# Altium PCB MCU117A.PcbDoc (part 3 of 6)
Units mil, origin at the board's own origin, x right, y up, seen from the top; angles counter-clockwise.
Board outline 2300 x 6749.64 mil, 6 copper layers (Top Signal, GND, Middle Signal, PWR, GND2, Bottom Signal), stack 61.64 mil thick; 424 components, 343 nets, 1563 pads, 921 vias.
Unrouted connection lines stored in the file: 4.
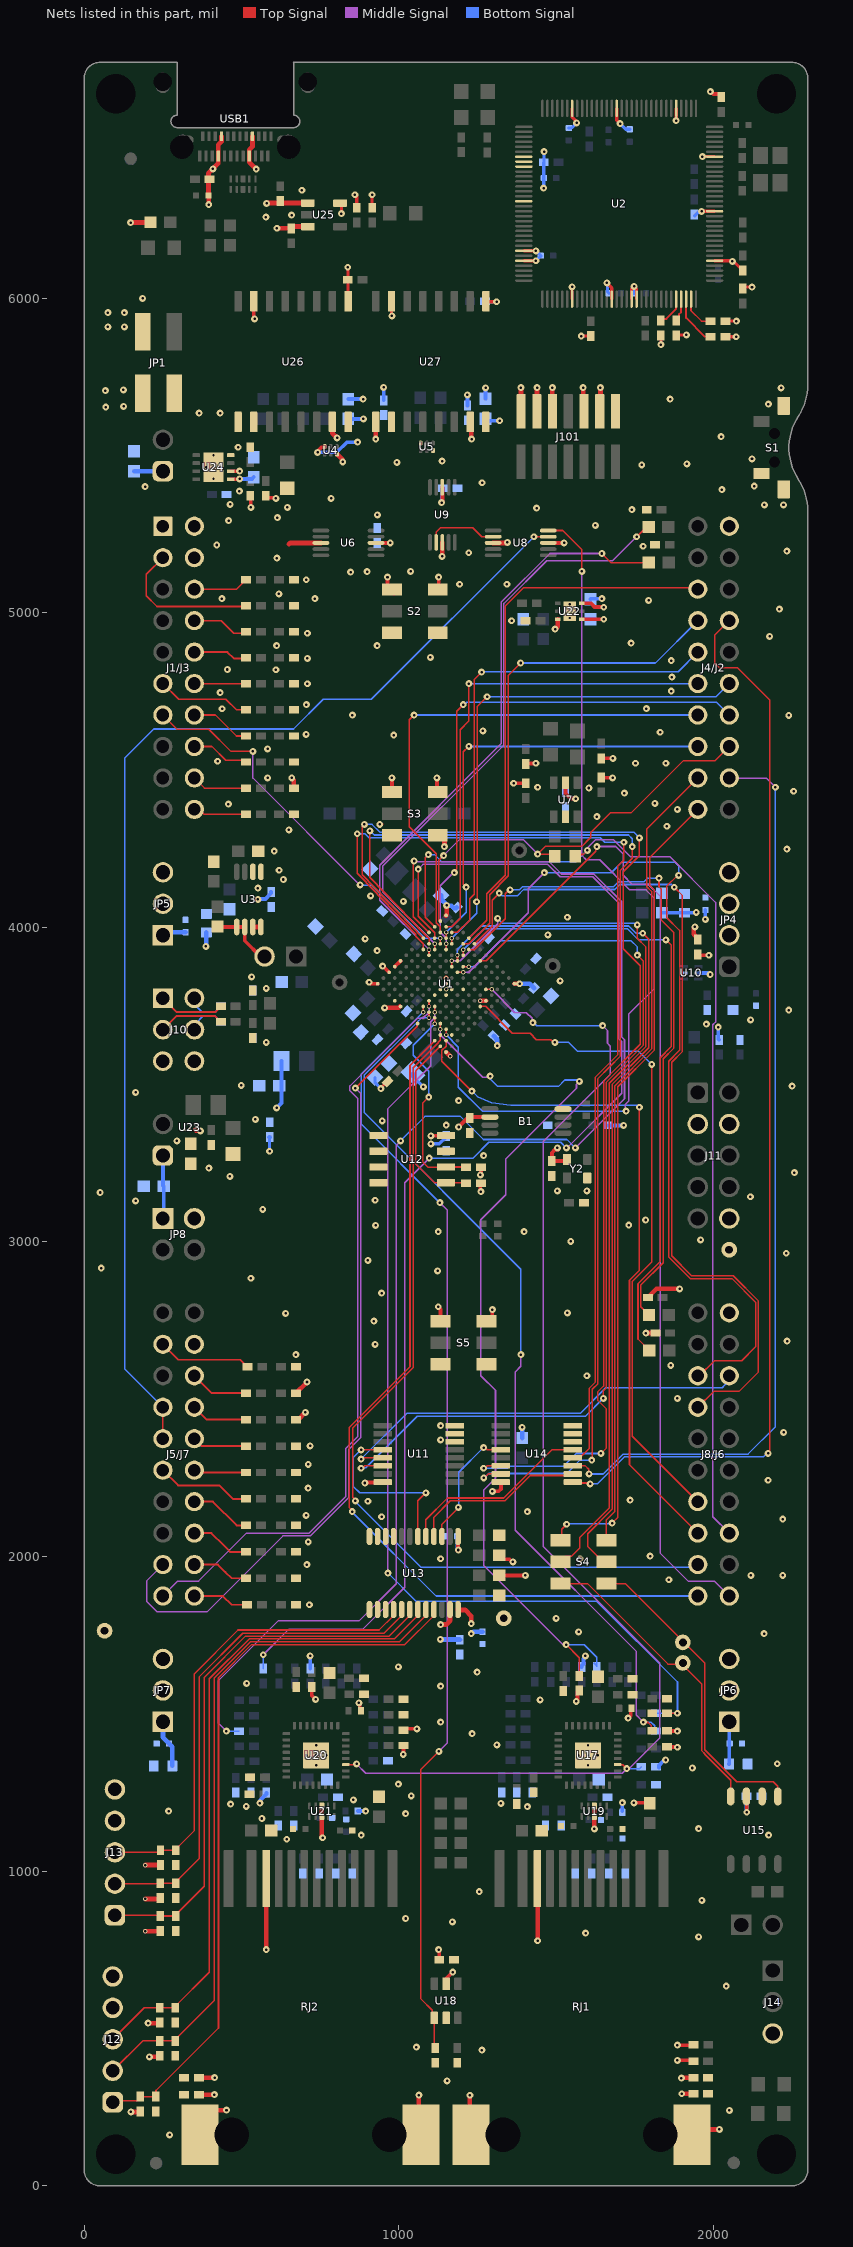
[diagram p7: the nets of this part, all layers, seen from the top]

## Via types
v1: diameter 22, hole 8, Top Signal to Bottom Signal, tented both sides, 821 vias
v2: diameter 14, hole 8, Top Signal to Bottom Signal, tented both sides, 82 vias
v3: diameter 19.68, hole 7.87, Top Signal to Bottom Signal, tented top, 14 vias
v4: diameter 15.75, hole 7.87, Top Signal to Bottom Signal, tented both sides, 2 vias
v5: diameter 19.68, hole 7.87, Top Signal to Bottom Signal, 2 vias

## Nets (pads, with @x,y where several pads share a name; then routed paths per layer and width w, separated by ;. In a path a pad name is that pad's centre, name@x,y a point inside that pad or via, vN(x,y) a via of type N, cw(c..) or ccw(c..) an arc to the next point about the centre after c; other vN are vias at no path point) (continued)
+3V3_ISO_JTAG: C130.1 C133.1 J101.1 R74.1 R76.1 U4.6 U5.6 U26.10 U26.16 U27.10 U27.16 | length 330
  Top Signal w12: v1(741.94,5509.65) 743.86,5511.56 743.86,5515.71 754.07,5525.92 763.86,5525.92 763.96,5526.02 U4.6@763.96,5527.8
  Bottom Signal w12: v1(741.94,5509.65) 802.41,5509.65 834.57,5541.81 v1(869.02,5541.81) ; R74.1@839.18,5678.86 v1(886.21,5678.86) ; v1(951.46,5715.99) 951.52,5715.93 C130.1@951.57,5674.88 C130.1@951.57,5674.88 ; v1(1217.84,5692.17) 1217.92,5692.08 1217.92,5658.7 C133.1@1218,5658.62 ; R76.1@1275.09,5679.5 1275.5,5679.91 v1(1275.5,5714.14)
+3V3_MCU: B1.6 C5.2 C12.2 C16.1 C17.2 C18.1 C19.1 C20.1 C21.1 C51.1 C60.1 C64.1 C78.2 C79.1 C83.2 C84.1 C85.1 C86.2 C103.1 C119.1 C122.1 C124.1 J1/J3.1 J11.10 J17.1 JP4.2 JP6.1 JP8.1 L2.1 L3.1 R12.2 R13.2 R14.2 R15.2 R24.1 R30.2 R34.2 R44.2 R47.2 R59.2 R74.2 R76.2 R85.2 R88.2 R89.2 R90.1 R105.2 R106.2 R107.2 R108.2 R111.2 R130.2 R131.1 R133.2 R134.2 R137.2 R138.1 R142.2 R145.2 R151.2 R166.1 R168.2 S2.1 S2.4 S3.3 S3.6 S5.3 S5.6 TP4.1 U3.1 U3.2 U6.8 U7.5 U8.8 U9.8 U10.2 U11.16 U12.8 U13.1 U14.16 U15.3 U18.5 U22.4 U22.6 U24.5 U24.6 Y2.4 | length 3761.1
  Top Signal w10: v1(943.05,3487.24) 943.05,3490.49 R44.2@959.49,3506.93
  Top Signal w12: U24.5@465.86,5423.92 493.03,5423.92 v1(494.01,5424.9) ; U24.6@465.86,5449.51 465.99,5449.64 v1(494.01,5449.64) ; R85.2@527.58,5371.65 529.3,5369.94 v1(529.3,5334.64) ; R90.1@576.92,5371.65 576.92,5370.72 582.73,5364.91 606.9,5364.91 v1(608.81,5363) ; R130.2@723.22,1585.69 723.22,1558.21 v1(735.32,1546.11) ; v1(873.11,1534.78) 873.11,1532.07 875.73,1529.45 875.73,1515.9 879.58,1512.06 R168.2@879.58,1510.09 ; v1(891.7,2233.85) 893.24,2235.38 947.58,2235.38 U11.16@949.11,2236.92 ; U6.8@927.34,5221.66 v1(972.41,5221.66) ; v1(963.76,5112.65) 963.76,5087.23 958.47,5081.93 957.76,5081.93 957.76,5065.15 978.37,5065.15 S2.1@983.66,5059.86 ; v1@977.68,4474.93 v1(977.96,4474.64) S3.6@977.96,4430.17 ; v1(1013.92,1371.59) 1014.38,1372.04 1014.38,1399.11 R133.2@1014.84,1399.57 ; R145.2@1014.84,1448.97 1018.51,1452.65 v1(1056.87,1452.65) ; v1(1101.57,3337.02) 1102.16,3337.6 1148.88,3337.6 U12.8@1149.46,3338.18 ; v1(1120.65,4474.64) 1120.65,4433.15 S3.3@1123.63,4430.17 ; v1(1125.14,2794.08) 1125.14,2793.43 1132.57,2786 S5.6@1132.57,2748.43 ; v1(1126,751.06) 1128.26,748.81 1128.26,719.12 C103.1@1128.38,719 ; v1(1126.45,5112.65) 1126.45,5076.42 S2.4@1129.33,5073.54 ; v1(1136,5350) 1138.18,5352.18 U9.8@1138.18,5398.49 ; U18.5@1150.22,641.99 1150.22,658.67 v1(1171.1,679.55) ; v1@1185.02,2020.86 1188.03,2023.87 U13.1@1188.03,2063.9 ; v1(1189.81,3365.31) 1221.42,3396.92 B1.6@1289.26,3396.92 ; R105.2@1256.36,3179.51 1258.83,3177.04 1258.83,3161.91 v1(1260.75,3160) ; v1(1259.27,3212.83) 1261.04,3214.6 R106.2@1261.04,3237.5 ; S5.3@1278.24,2748.43 1283.31,2748.43 1297,2762.12 v1(1297,2785) ; v1(1297,2207.42) 1317.13,2207.42 1324.16,2214.45 U14.16@1324.16,2236.92 ; R34.2@1318.46,1940.4 1318.67,1940.19 v1(1402.02,1940.19) ; R30.2@1318.89,2004.39 1331.59,1991.69 1351.26,1991.69 1359.61,1983.34 v1(1362.31,1983.34) ; v1(1364.43,4457.76) R14.2@1403.55,4457.76 ; R12.2@1403.55,4519.53 1404.42,4520.39 1434.84,4520.39 v1(1435.7,4521.25) ; U8.8@1474.6,5221.66 v1(1524.9,5221.66) ; v1@1507.7,3295.42 1505.79,3293.5 1496.27,3293.5 1486.44,3283.67 1486.44,3258.08 C20.1@1485.31,3256.95 1528.14,3256.95 Y2.4@1533.71,3262.52 ; U7.5@1529.55,4459.8 1529.55,4425.35 1545.45,4409.46 1560.54,4409.46 v1(1561.5,4408.49) ; v1(1563.66,1540.03) 1563.66,1542.74 1567.36,1546.44 1567.36,1568.03 R88.2@1573.17,1573.84 ; U22.4@1581.6,4979.05 v1(1651,4979.05) ; U22.6@1581.6,5030.23 1609.8,5030.23 1622,5018.03 1650.04,5018.03 v1(1651,5017.07) ; R15.2@1643.14,4476.39 1644.01,4475.51 1678.12,4475.51 v1(1678.99,4474.64) ; R13.2@1643.48,4536.97 v1@1679.97,4536.97 ; v1@1726.85,1490.84 v1@1728.5,1490.84 ; v1(1728.5,1486.41) 1736.91,1494.81 1736.91,1517.96 R134.2@1740.75,1521.8 ; R89.2@1852.62,1395 1853.18,1394.44 1884.84,1394.44 v1(1885.4,1393.88) ; R111.2@1857.31,1445.25 1857.68,1445.63 1885.03,1445.63 v1(1885.4,1445.25) ; v1(1885.4,398.92) 1932.94,398.92 R138.1@1935.7,396.16 ; v1(1885.4,447.15) 1934.46,447.15 R137.2@1935.86,448.55 ; C124.1@1949.99,3913.53 1952.36,3911.17 v1(1985.29,3911.17) ; U15.3@2104.49,1237.59 2105.52,1236.56 v1(2105.52,1187.36)
  Bottom Signal w10: v1(588.76,3288.18) C17.2@588.76,3332.71 ; C64.1@924.5,3522.92 924.5,3505.8 v1(943.05,3487.24) ; L3.1@1045.01,3526.73 1045.01,3525.59 v1(1077.57,3493.03) ; v1(1101.57,3311.88) 1128.75,3311.88 1149.95,3333.08 C86.2@1149.95,3337.02
  Bottom Signal w12: JP8.1@249.99,3074.64 252.5,3077.15 C119.1@252.5,3177 249.99,3179.5 J17.1@249.99,3274.64 ; v1(494.01,5424.9) 532.86,5424.9 C122.1@538.77,5430.81 ; v1@555.01,4088.43 556.93,4090.34 575.68,4090.34 593.77,4108.43 C51.1@593.77,4112.37 ; v1(558.23,1216.27) 560.14,1218.18 560.14,1226.8 579,1245.66 R151.2@579,1249.6 ; v1(611.17,3425.71) 627.14,3441.68 L2.1@627.14,3575.24 ; R142.2@717.94,1643.85 v1(717.94,1684.59) ; R74.2@839.18,5615.87 v1(887,5615.87) ; R166.1@869.42,1191.4 893.61,1191.4 v1(894,1191) ; C12.2@931.57,5221.67 v1(972.41,5221.66) ; v1(1136,5350) 1136,5392.35 C18.1@1139.29,5395.64 ; C21.1@1185.62,2064.78 1185.62,2024.23 v1(1188.99,2020.86) ; R76.2@1275.09,5616.51 1281.6,5610 v1(1320,5610) ; C16.1@1529.55,4429.29 1529.55,4425.35 1544.5,4410.41 1559.59,4410.41 v1(1561.5,4408.49) ; R108.2@1580.66,1648.64 1580.66,1652.57 1586.48,1658.38 1586.48,1675.57 1592.78,1681.88 v1(1592.78,1684.59) ; C85.1@1608.79,5042.5 1610.84,5044.54 1644.65,5044.54 v1(1645.07,5044.96) ; R24.1@1665.1,3370.36 v1@1713.89,3370.36 ; R131.1@1710.15,1191 v1(1710.15,1217.97) ; R107.2@1826.32,1329.58 1826.32,1336.17 1841.7,1351.55 1845.46,1351.55 v1(1847.37,1353.47) ; R47.2@1836.27,4046.3 C78.2@1908.11,4046.3 ; C78.2@1908.11,4046.08 1943.68,4046.08 v1(1944.99,4047.39) ; U10.2@1951.62,3855 1981.45,3855 1986.5,3849.96 v1(1989.2,3849.96) ; v1(1974,4025) C79.1@1974,4055.32 ; v1(2014.86,3683.07) 2014.86,3645.31 R59.2@2017.76,3642.41 ; C83.2@2049.47,1341.01 2049.99,1341.53 JP6.1@2049.99,1474.64 ; C5.2@2104.94,1237.59 2104.94,1187.95 v1(2105.52,1187.36)
  Bottom Signal w15: C17.2@588.76,3332.71 C17.2@589.08,3333.03 ; L3.1@1045.01,3526.73 L3.1@1045.01,3534.79
  other v1: 1503.73,3298.62 1713.89,3370.36 551.64,4088.43 551.64,4124.38 632.71,4151.89 619.48,4181.35 1680,4537 613.91,5301.8 463.67,5344 493.18,5386.03
+3V3_XDS110: C126.1 C129.1 C132.1 C134.2 C135.2 C136.2 C137.2 C138.2 C139.1 C140.1 C141.2 R16.2 R96.1 R101.2 R102.2 R103.2 R104.2 R174.2 R177.2 U2.7 U2.8 U2.9 U2.16 U2.26 U2.28 U2.39 U2.47 U2.51 U2.52 U2.69 U2.79 U2.90 U2.101 U2.113 U2.122 U25.5 U26.1 U26.7 U27.1 U27.7 | length 1508.4
  Top Signal w10: U26.7@538.77,5989.93 538.77,5936.49 v1(541.62,5933.64) ; U25.5@812.87,6301.79 817.36,6297.3 v1(817.36,6268.47) ; v1(837.49,6097.89) 838.77,6096.62 U26.1@838.77,5989.93 ; v1(860.05,6328.14) 865.81,6322.39 C126.1@865.81,6287.01 ; R96.1@914.88,6286.04 v1(914.88,6328.14) ; U27.7@976.45,5989.93 976.45,5944.1 v1(977.41,5943.14) ; U27.1@1276.45,5989.93 1278.18,5988.2 v1(1310.86,5988.2) ; U2.28@1397.04,6118.54 v1(1435.7,6118.54) ; U2.26@1397.04,6150.04 v1(1435.7,6150.04) ; U2.39@1550.58,5996.49 v1(1550.58,6035.15) ; U2.122@1550.58,6602.79 1550.58,6574.31 1565.09,6559.81 v1(1565.09,6556.56) ; v1(1579.47,5878.98) R16.2@1609.46,5878.98 ; v1(1660.82,6048.04) 1676.57,6032.3 U2.47@1676.57,5996.49 ; U2.113@1692.32,6602.79 1692.32,6564.84 v1(1703.05,6554.11) ; U2.51@1739.56,5996.49 1739.56,6029.44 v1(1747.38,6037.26) 1755.31,6029.33 U2.52@1755.31,5996.49 ; v1(1832.55,5851.84) 1832.59,5851.88 R104.2@1832.59,5880.73 R104.2@1832.59,5883.6 ; v1(1881.29,6564.13) U2.101@1881.29,6602.79 ; R103.2@1881.73,5881.04 1883.2,5882.5 v1(1913.56,5882.5) ; v1@1963.3,6275.75 U2.79@2003.57,6275.75 ; v1(1964.68,6449.25) U2.90@2003.34,6449.25 ; U2.69@2003.34,6118.54 2057.56,6118.54 v1(2059.6,6116.5) 2063.41,6116.5 R174.2@2092.28,6087.64 ; R102.2@2037.8,5876.99 2037.92,5876.87 v1(2071.67,5876.87) ; R101.2@2037.8,5926.74 v1(2072.69,5926.74) ; R177.2@2092.28,6029.62 2097.22,6034.56 v1(2122.24,6034.56)
  Bottom Signal w10: C132.1@1273.57,5989.93 1275.3,5988.2 v1(1310.86,5988.2) ; v1(1435.7,6118.54) 1449.91,6132.75 1450.74,6132.75 1450.74,6135 v1(1435.7,6150.04) ; v1(1460.13,6349.54) 1460.35,6349.76 1460.35,6379.67 1460.13,6379.89 1460.57,6380.34 1460.57,6430.83 1461.49,6431.75 v1(1461.49,6465) ; C135.2@1539.99,6540.44 1548.96,6540.44 v1(1565.09,6556.56) ; v1(1660.82,6048.04) 1663.12,6045.75 1663.12,6019.47 C137.2@1667.67,6014.92 ; v1(1703.05,6554.11) 1720.93,6536.22 C134.2@1733.74,6536.22 ; C139.1@1939.2,6260.15 1955.07,6276.02 1955.98,6275.11 v1(1962.16,6275.11)
  Bottom Signal w11.81: C136.2@1745.58,6014.92 1746.89,6016.22 1746.89,6036.77 v1(1747.38,6037.26)
+5V0_MCU: C22.2 C23.1 C76.2 C77.1 C81.2 C82.1 C120.1 C121.1 J1/J3.21 J12.4 J13.4 J16.1 JP1.2 JP5.1 JP7.1 JP8.2 R5.2 R6.2 R7.2 R8.2 R9.2 R10.2 R82.2 TP5.1 U13.23 U13.24 U23.B2 U23.C2 | length 857.2
  Top Signal w15: v1(148,235) 176.97,235 R5.2@178.35,236.38 ; v2(194.17,809.48) 240.76,809.48 R8.2@241.65,810.38 ; v2(194.17,911.73) 239.16,911.73 R9.2@241.81,914.38 ; v2(194.17,1019.43) R10.2@242.31,1019.43 ; v1(203,517) 237.83,517 R7.2@239.63,518.81 ; v1(207,410) 236.16,410 R6.2@239.63,413.47 ; v1(1132.57,1783.86) 1149.96,1783.86 1162.44,1796.35 U13.23@1162.44,1831.61 ; U13.24@1188.03,1831.61 1188.03,1831.53 1189.29,1830.27 1210.6,1830.27 1230,1810.87 v1(1230,1787)
  Bottom Signal w15: C121.1@158.49,5449.51 249.86,5449.51 J16.1@249.99,5449.64 ; JP7.1@249.99,1474.64 249.99,1425.48 C82.1@269.68,1405.79 279.82,1395.65 C81.2@279.82,1334.86 ; JP5.1@249.99,3974.64 259.66,3984.32 C77.1@322,3984.32 ; v1(386.44,3939.08) 388,3940.65 C76.2@388,3983.47 ; v1(1132.08,1736.68) 1132.61,1736.15 1193.47,1736.15 C23.1@1194,1735.62 ; v1(1230,1755.06) 1236.01,1761.07 C22.2@1265.71,1761.07
  other v1: 396,3234.65 294.11,3321.46 193.68,5400.64 68.23,5652.96 125.23,5655.46 67.36,5705.5 124.37,5708
+5V0_USB: C80.2 C127.1 C128.1 JP1.1 R68.2 R69.2 R164.1 U25.1 U25.3 USB1.A4 USB1.A9 USB1.B4 USB1.B9 | length 698.9
  Top Signal w11.81: v1(1990,6656.29) 1991.6,6656.29 1999.43,6648.46 2018.68,6648.46 2024.59,6642.56 R164.1@2024.59,6638.62
  Top Signal w15: v1(147.24,6239.53) 147.73,6240.02 210.14,6240.02 R69.2@210.63,6240.51 ; v1(395.66,6296.63) 395.66,6324.99 C80.2@394.71,6325.94 394.71,6396.25 v1(409.09,6410.63) 426.17,6427.71 426.17,6487.17 436.02,6497.01 USB1.B4@436.02,6514.21 ; USB1.B9@534.44,6514.21 534.44,6481.51 524.6,6471.66 524.6,6431.84 v1(546.7,6409.73) ; v1(579.53,6300.52) 580.87,6301.86 618.64,6301.86 C127.1@622.95,6306.17 ; v1(612.34,6221.64) C128.1@657.67,6221.64 ; C127.1@622.95,6307.88 C127.1@622.95,6306.17 ; C128.1@657.67,6221.43 657.67,6222.68 661.98,6226.99 U25.3@710.5,6226.99 ; U25.1@710.5,6301.79 710.41,6301.89 627.26,6301.89 C127.1@622.95,6306.2
  other v1: 75.05,5908.05 127.55,5908.05 75.05,5953.51 127.55,5953.51 185.61,5999.04 577.16,6256.89 658.91,6263.64 691.91,6342.59
ADC_VREF: J15.2 R66.2 U3.5 U3.6 | length 214.8
  Top Signal w12: R66.2@423.52,4002.51 424.88,4001.15 U3.5@484.52,4001.15 U3.6@510.11,4001.15 510.11,3957.38 560.36,3907.14 J15.2@573.14,3907.14
ADCINA0/DACA_OUT: J1/J3.30 R18.1 | length 171.5
  Top Signal w5: J1/J3.30@349.99,4374.64 364.88,4374.64 380.28,4359.25 R18.1@515.1,4359.25
ADCINA4: J1/J3.24 R38.1 | length 180.5
  Top Signal w5: J1/J3.24@349.99,4974.64 434.99,4974.64 474.99,4934.64 R38.1@513.97,4934.64
ADCINA5: J5/J7.42 R39.1 | length 297.9
  Top Signal w6: J5/J7.42@249.99,2674.64 298.94,2625.69 496.13,2625.69 R39.1@518.38,2603.44
ADCINA7: J1/J3.27 R40.1 | length 191.5
  Top Signal w5: J1/J3.27@349.99,4674.64 416.98,4674.64 483.54,4608.08 R40.1@513.97,4608.08
ADCINA8: J5/J7.64 R41.1 | length 180.3
  Top Signal w6: J5/J7.64@349.99,2474.64 389.29,2435.35 R41.1@513.97,2435.35
ADCINA10: J5/J7.67 R42.1 | length 195.2
  Top Signal w6: J5/J7.67@349.99,2174.64 408.64,2174.64 484.13,2099.15 504.19,2099.15 R42.1@513.97,2099.15
ADCINA14/B14/C14: J1/J3.23 R43.1 | length 176.4
  Top Signal w5: J1/J3.23@349.99,5074.64 483.97,5074.64 R43.1@513.97,5104.64
ADCINA15/B15/C15: J5/J7.63 R45.1 | length 186.9
  Top Signal w6: J5/J7.63@349.99,2574.64 405.24,2519.39 R45.1@513.97,2519.39
ADCINB0/VDAC: J1/J3.2 R46.1 | length 472.4
  Top Signal w5: J1/J3.2@249.99,5174.64 197.12,5121.77 197.12,5053.78 231.25,5019.64 R46.1@512.65,5019.64
ADCINB1/DACC_OUT: J5/J7.70 R48.1 | length 178.8
  Top Signal w6: J5/J7.70@349.99,1874.64 440.72,1874.64 468.37,1847 R48.1@517.38,1847
ADCINB3: J5/J7.65 R49.1 | length 173.6
  Top Signal w6: J5/J7.65@349.99,2374.64 373.34,2351.3 R49.1@513.97,2351.3
ADCINB4: J1/J3.25 R50.1 | length 172.3
  Top Signal w6: J1/J3.25@349.99,4874.64 454.99,4874.64 474.99,4854.64 R50.1@513.97,4854.64
ADCINB6: J5/J7.68 R51.1 | length 188.6
  Top Signal w6: J5/J7.68@349.99,2074.64 403.85,2074.64 442.61,2035.88 463.39,2015.1 R51.1@513.97,2015.1
ADCINB7: J1/J3.28 R52.1 | length 182.1
  Top Signal w5: J1/J3.28@349.99,4574.64 405.7,4574.64 449.48,4530.86 R52.1@513.97,4530.86
ADCINB8B9_N: J10.3 R55.1 | length 210
  Top Signal w6: J10.3@249.99,3674.64 293.99,3718.64 415.24,3718.64 R55.1@434.01,3699.87
ADCINB8B9_P: J10.1 R54.1 | length 209.7
  Top Signal w6: J10.1@249.99,3774.64 293.99,3730.64 416.02,3730.64 R54.1@434.01,3748.62
ADCINC0: J1/J3.6 R56.1 | length 298.6
  Top Signal w5: J1/J3.6@249.99,4774.64 299.99,4724.64 449.99,4724.64 483.6,4691.04 R56.1@513.97,4691.04
ADCINC1: J5/J7.46 R57.1 | length 301.9
  Top Signal w6: J5/J7.46@249.99,2274.64 298.22,2226.41 428.73,2226.41 471.95,2183.2 R57.1@513.97,2183.2
ADCINC4: J1/J3.26 R60.1 | length 164
  Top Signal w5: J1/J3.26@349.99,4774.64 R60.1@513.97,4774.64
ADCINC5: J5/J7.66 R61.1 | length 167
  Top Signal w6: J5/J7.66@349.99,2274.64 357.39,2267.25 R61.1@513.97,2267.25
ADCINC6: J5/J7.69 R62.1 | length 182
  Top Signal w6: J5/J7.69@349.99,1974.64 424.6,1974.64 448.36,1950.88 468.19,1931.05 R62.1@513.97,1931.05
ADCINC7: J1/J3.29 R63.1 | length 177.3
  Top Signal w5: J1/J3.29@349.99,4474.64 382.07,4442.57 R63.1@513.97,4442.57
ADCINC8C9_N: J10.4 R65.1 | length 123.4
  Bottom Signal w5.91: J10.4@349.99,3674.64 349.99,3693.62 353.52,3693.62 378.54,3718.64 415.24,3718.64 421.21,3712.67 421.21,3708.73 430.07,3699.87 R65.1@434.01,3699.87
ADCINC8C9_P: J10.2 R64.1 | length 132.4
  Bottom Signal w5.91: 375.07,3730.64 416.02,3730.64 421.21,3735.83 421.21,3739.77 427.07,3745.62 431.01,3745.62 R64.1@434.01,3748.62
  Bottom Signal w6: J10.2@349.99,3774.64 349.99,3755.72 375.07,3730.64 ; R64.1@431.01,3740.52 431.01,3745.62 R64.1@434.01,3748.62
DEBUG_ID4: R101.1 U2.63 | length 112.4
  Top Signal w5: 1928.54,5959.74 1961.54,5926.74 R101.1@1990.56,5926.74
  Top Signal w6: 1928.54,5959.74 U2.63@1928.54,5996.49
DEBUG_ID5: R102.1 U2.62 | length 162.2
  Top Signal w6: U2.62@1912.79,5996.49 1912.79,5936.94 1972.74,5876.99 R102.1@1990.56,5876.99
DEBUG_ID6: R103.1 U2.61 | length 79.9
  Top Signal w6: R103.1@1882.14,5922.76 1889.98,5930.61 1889.98,5948.31 1896.68,5955.01 1896.68,5996.13 U2.61@1897.04,5996.49
DEBUG_ID7: R104.1 U2.60 | length 99.4
  Top Signal w6: R104.1@1833.02,5922.01 1833.02,5925.52 1841.4,5933.9 1849.89,5933.9 1862.92,5946.93 1881.29,5965.3 U2.60@1881.29,5996.49
EQEP1A: C6.1 J12.1 R5.1 U13.21 | length 2345.9
  Top Signal w5: J12.1@90.6,265.65 94.83,269.87 168.54,269.87 178.35,279.68 R5.1@178.35,283.62 C6.1@227.35,283.62 228.03,284.31 228.03,303.03 426.53,501.52 426.53,1615.12 531.74,1720.34 1018.69,1720.34 1111.26,1812.91 U13.21@1111.26,1831.61
EQEP1B: C7.1 J12.2 R6.1 U13.20 | length 2216.2
  Top Signal w5: J12.2@90.6,365.65 185.67,460.72 R6.1@239.63,460.72 C7.1@288.63,460.72 288.63,464.66 413.72,589.75 413.72,1615.05 528.02,1729.34 1002.1,1729.34 1085.67,1812.91 U13.20@1085.67,1831.61
EQEP1I: C8.1 J12.3 R7.1 U13.19 | length 2094.9
  Top Signal w5: J12.3@90.6,465.65 191,566.05 R7.1@239.63,566.05 C8.1@288.63,566.05 288.63,569.99 397.49,678.85 397.49,1611.54 524.29,1738.34 985.51,1738.34 1060.08,1812.91 U13.19@1060.08,1831.61
EQEP2A: C9.1 J13.1 R8.1 U13.18 | length 1751.7
  Top Signal w5: J13.1@103.02,865.74 J13.1@97.33,860.05 239.23,860.05 R8.1@241.65,857.62 C9.1@290.65,857.62 290.65,861.56 381,951.91 381,1615.65 512.69,1747.34 968.91,1747.34 1034.49,1812.91 U13.18@1034.49,1831.61
EQEP2B: C10.1 J13.2 R9.1 U13.17 | length 1640.6
  Top Signal w5: J13.2@97.33,976.43 J13.2@97.33,960.05 240.24,960.05 R9.1@241.81,961.62 C10.1@290.81,961.62 290.81,965.56 365,1039.75 365,1617.37 503.97,1756.34 952.32,1756.34 1008.9,1812.91 U13.17@1008.9,1831.61
EQEP2I: C11.1 J13.3 R10.1 U13.16 | length 1510.9
  Top Signal w5: J13.3@97.33,1060.05 235.69,1060.05 R10.1@242.31,1066.67 C11.1@291.31,1066.67 291.31,1070.61 349.99,1129.29 349.99,1627.95 488.58,1766.54 936.93,1766.54 983.31,1812.91 U13.16@983.31,1831.61
ERRORSTS: U1.L12
ETH1_EARTH: C101.2 C117.2 R136.2 R170.2 RJ1.10 RJ1.13 RJ1.14 RJ2.10 RJ2.13 RJ2.14 | length 1081.1
  Top Signal w15: R170.2@364.62,289.81 v1(413.72,289.81) ; C117.2@364.62,343.81 v1(414.26,343.81) ; RJ2.14@367.66,162 367.66,189.04 419.22,240.59 v1(452.05,240.59) ; v1(578.29,751.06) RJ2.10@578.29,976.57 ; v1(1063.29,288.52) 1063.29,168.74 RJ2.13@1070.02,162 ; v1(1225.51,287.83) 1225.51,165.87 RJ1.14@1229.38,162 ; RJ1.10@1440.01,976.57 1441,975.57 v1(1441,779) ; v1(1897.7,342.45) 1899.25,344 C101.2@1935.7,344 ; v1(1899.05,292.73) 1899.31,293 R136.2@1935.7,293 ; RJ1.13@1931.74,162 1948.95,179.21 v1(2018.58,179.21)
GND: B1.4 C1.2 C2.2 C3.2 C4.2 C5.1 C6.2 C7.2 C8.2 C9.2 C10.2 C11.2 C12.1 C13.2 C14.2 C15.2 C16.2 C17.1 C18.2 C19.2 C20.2 C21.2 C22.1 C23.2 C26.2 C27.2 C28.2 C29.2 C30.2 C31.2 C32.2 C33.2 C34.2 C35.2 C36.2 C37.2 C38.2 C39.2 C40.2 C41.2 C42.2 C43.2 C44.2 C45.2 C46.2 C47.2 C48.2 C49.2 C50.2 C51.2 C52.2 C53.2 C54.2 C55.2 C56.2 C57.2 C58.2 C59.2 C60.2 C61.2 C62.2 C64.2 C65.2 C66.2 C67.2 C68.2 C69.2 C70.2 C71.2 C72.2 C73.2 C74.1 C75.1 C76.1 C77.2 C78.1 C79.2 C81.1 C82.2 C83.1 C84.2 C85.2 C86.1 C87.1 C88.1 C89.2 C90.2 C91.2 C92.2 C93.2 C94.2 C95.1 C96.1 C97.2 C98.2 C99.2 C100.2 C101.1 C102.1 C103.2 C104.1 C105.2 C106.2 C107.2 C108.2 C109.2 C110.2 C111.1 C112.1 C113.2 C114.1 C115.2 C116.1 C117.1 C118.2 C119.2 C120.2 C121.2 C122.2 C123.2 C124.2 C125.2 C130.2 C133.2 J1/J3.22 J4/J2.20 J5/J7.62 J8/J6.60 J10.5 J10.6 J11.3 J11.4 J12.5 J13.5 J14.3 J101.3 J101.5 J101.9 J101.11 J101.13 JP1.4 JP4.3 JP4.4 JP5.2 JP5.3 JP6.2 JP6.3 JP7.2 JP7.3 LED3.1 LED6.1 R23.1 R26.1 R32.1 R35.1 R36.2 R37.2 R53.1 R67.1 R79.1 R94.1 R109.1 R112.1 R113.1 R123.1 R124.1 R125.1 R127.1 R128.1 R129.1 R132.1 R135.1 R136.1 R139.2 R140.2 R141.1 R143.1 R146.1 R147.1 R159.1 R160.1 R161.1 R162.1 R163.2 R167.1 R169.1 R170.1 S1.1 S1.2 S1.3 S2.3 S2.6 S3.1 S3.4 S5.1 S5.4 TP6.1 U1.A1 U1.A13 U1.E12 U1.F9 U1.G7 U1.G8 U1.H7 U1.H8 U1.J1 U1.J7 U1.K1 U1.L1 U1.N1 U1.N4 U1.N5 U1.N13 U3.7 U3.8 U4.3 U5.3 U6.3 U7.2 U8.3 U9.3 U10.5 U11.6 U11.7 U11.8 U12.1 U12.2 U12.3 U12.4 U12.7 U13.9 U13.10 U13.11 U13.12 U13.13 U13.14 U13.15 U14.6 U14.7 U14.8 U15.2 U17.33@1600.99,1368.2 U18.2 U19.3@1620.99,1207.44 U19.8@1620.99,1174.56 U20.33@736.84,1368.2 U21.3@755,1207.44 U21.8@755,1174.56 U22.3 U22.7 U23.A2 U24.8 U24.9 U26.9 U26.15 U27.9 U27.15 Y2.2 | length 1852.4
  Top Signal w12: U23.A2@351.5,3357 355.52,3352.97 v1(369.37,3352.97) ; v1(905.56,3825.39) 910.27,3820.69 U1.N1@932.81,3820.69 ; v1@949.51,3876.37 U1.L1@969,3856.88 ; U1.K1@987.09,3874.98 U1.J1@1005.19,3893.07 ; v1(1747.12,1217.46) 1795.8,1217.46 R135.1@1797.04,1216.23
  Top Signal w15: U3.7@535.7,4001.15 U3.8@561.29,4001.15 ; 650.43,5217.41 654.69,5221.66 U6.3@752.14,5221.66 ; v1(659.51,4474.64) 666.05,4468.1 C37.2@666.05,4442.57 ; C30.2@672.54,2519.39 v1(707.9,2554.82) v1(707.9,2554.82) ; C41.2@681.86,2436.91 v1(702.9,2457.95) ; U21.3@755,1207.44 U21.8@755,1174.56 755,1108.73 v1(757.49,1106.24) ; U26.15@788.77,5606.07 788.77,5570.15 v1(803.33,5555.59) ; U4.3@803.33,5504.17 821.49,5486.01 v1(821.49,5479.49) ; v1(926.45,5551.67) U27.9@926.45,5606.07 ; v1(939.15,4327.06) v1@943.28,4327.06 ; v1(954.33,3743.93) 998.56,3743.93 U1.N5@1002.83,3748.2 ; S3.1@1123.63,4292.38 1132.44,4292.38 1144.63,4280.19 v1(1144.63,4256.72) ; v1(1137.57,5179.11) 1138.18,5179.73 U9.3@1138.18,5223.29 ; U1.A1@1149.95,4037.83 1151.71,4039.59 v1(1151.71,4069.71) ; U1.N13@1150.36,3603.14 1151.14,3602.36 1151.14,3602.12 v2(1163.49,3589.77) ; U27.15@1226.45,5606.07 1229.66,5602.86 1229.66,5553.01 v1(1231,5551.67) ; v2(1258.52,3766.4) 1258.63,3766.3 U1.E12@1276.62,3766.3 ; U8.3@1299.4,5221.66 1343.12,5221.66 v1(1344.75,5223.29) ; U1.A13@1367.09,3820.69 v1(1383.61,3820.69) ; v1(1387.77,5715.12) 1387.77,5640.41 J101.13@1388.46,5639.72 ; J101.11@1438.46,5639.72 1439.01,5640.27 v1(1439.01,5715.12) ; v1(1487.59,5715.12) 1487.59,5640.59 J101.9@1488.46,5639.72 ; v1@1497.57,4947.99 1504.83,4955.26 U22.3@1504.83,4979.05 ; v1(1585.64,5715.12) 1585.64,5642.54 J101.5@1588.46,5639.72 ; U19.3@1620.59,1207.44 1620.59,1134.78 v1(1620.99,1134.38) ; J101.3@1638.46,5639.72 1640.41,5641.67 v1(1640.41,5715.12) ; v1(1785.1,2710.54) C4.2@1814.99,2710.54 ; C3.2@1791.06,2823.34 1818.73,2851 v1(1892.17,2851) ; v1(1940.55,4001.39) 1940.55,3999.5 1937.25,3996.19 1937.25,3977.46 1949.99,3964.71 C124.2@1949.99,3960.77
  Bottom Signal w15: C54.2@1134.29,4101.65 1134.29,4089.02 1151.71,4071.6 v1(1151.71,4069.71) 1153.04,4068.37 1167.18,4068.37 1175.11,4060.44 1181.2,4060.44 C56.2@1183.99,4063.23 ; C57.2@1301.12,3654.6 1312.53,3643.19 v1(1312.53,3623.99) ; v1(1383.61,3820.69) 1415.4,3820.69 C73.2@1429.44,3806.65 ; R37.2@1391.77,2376.68 v1(1391.77,2410.71)
  other v1: 271.21,162 2050.51,240 1153.37,333.39 1263.63,431.73 1055.81,441.18 2040.38,634.99 1952.47,791.39 1593.45,803.55 1170,839 1021.43,849.71 1963,907.41 1255.47,935.45 643.52,1101.56 880.35,1114.71 2175.13,1114.71 1952.47,1135.3 564.62,1167.55 1021.43,1183 267.77,1191.2 1408.61,1205.02 514.79,1205.85 465.13,1213.44 1324.16,1215.61 855.64,1226.5 1039.21,1239.15 998.11,1276.52 1932.94,1328.06 2202.46,1341.53 1311.13,1401.58 1232.6,1437.1 1132.57,1473.7 1448.86,1544.32 1132.57,1588.38 516.25,1597.01 1248.86,1632.93 998.11,1649.44 2161,1755 1571.08,1760.65 1499.61,1803.79 715.63,1847 1857.99,1926.39 2118.77,1940.19 2220,1940.19 707.32,1974.64 1132.57,1993 1575,1993 1798.51,2001.49 711.95,2046.39 2220,2119 945.12,2126.5 705.35,2130.91 1408.6,2142.8 901.54,2175.74 1734.76,2179.29 711.69,2217.88 2173.18,2242.56 711.95,2293.04 717.94,2351.49 1132.57,2371.04 2223,2395 1132.57,2416.05 1885,2503 1597.2,2574.64 1863.9,2607.92 672.89,2642 924.46,2674.64 2234,2685 920.2,2748.43 639.89,2773.12 1535.44,2774.64 945.12,2837.14 529.77,2884.56 1123,2908 53.99,2917.13 901.54,2941.52 2231,2964 1546.25,3001.83 1958.77,3006.34 1125.14,3032.89 1397.88,3032.89 925.74,3052.32 1730.45,3053.41 1784.25,3069.71 567.37,3103.7 163.49,3130.55 924.46,3132.56 2117.29,3143.66 50.26,3157.11 1503.84,3161.91 1597.71,3161.91 463,3208.43 2256.72,3220.43 1269,3274.64 1150.36,3371.45 947.16,3384.88 543.97,3389.23 1189.81,3449.19 163.49,3475 2249.52,3495.08 498.86,3497.66 578.34,3634.12 1977,3692.22 2117.92,3705.88 2239.09,3736.87 578.34,3805.95 1512.42,3829.66 532.01,3842.6 948.44,3876.37 930.89,3926.09 892.89,3963.42 1473.6,3975.97 1535.8,4031.92 1014.08,4082.13 910.27,4099.56 603.81,4242.04 2233.18,4248.42 650.43,4309.4 1851.72,4321.09 1629.27,4351.53 1885.4,4374.64 458.13,4391.36 1813.67,4393.6 1716.66,4426.49 2254.76,4432.48 1604.03,4442.73 1441,4445 582.73,4474.64 1751.95,4521.25 1848.77,4521.25 423.52,4527.62 582.73,4567.16 983.56,4611.05 704.97,4613.13 1830,4620 1266.65,4624.45 2239.09,4673.54 852.45,4674.64 438.38,4694.6 1786.89,4694.93 706.13,4707.62 431.61,4746 1865.66,4750.71 709.3,4774.14 1867.59,4795.19 454.99,4819.33 608.81,4818.5 1865.66,4847.5 709.3,4854.64 1099.88,4858.01 611.33,4895 930.89,4894.96 1738.01,4903.43 2178.3,4924.41 709.3,4934.64 1496.52,4947.99 1358.08,4974.17 2209,5011 1793.64,5039.13 437.28,5044.96 733.3,5044.96 618.81,5059.86 1192.88,5090.23 1343.12,5090.23 705.59,5104.64 846.55,5128.65 898.92,5130.72 1037.43,5131 612.37,5173.66 1221.94,5190.33 2233.18,5195.9 1776,5211 420.98,5215 1624.45,5277.1 458.85,5292.73 931.57,5311 1740.62,5327.3 1437.98,5332.15 645.34,5334.64 2161.85,5342.2 2222.36,5342.2 784.69,5363 2026.66,5390.84 2129.31,5402.18 1264.22,5412.88 1771.86,5469.6 1914.99,5473.03 993.41,5477.8 1137.57,5481.69 2122.24,5488.86 488.77,5525.58 2024.12,5559.6 365.32,5634.46 431.61,5633.93 2174.19,5662.52 1862.01,5678.86 2214.74,5714.14
  other v2: 1149.95,3802.59 1149.95,3838.79
  other v3: 736.84,1336.7 1600.99,1336.7 705.35,1368.2 768.34,1368.2 1569.5,1368.2 1632.49,1368.2 736.84,1399.7 1600.99,1399.7 1543.22,4982.99 1543.22,5026.3 410.74,5424.9 388.1,5462.3 433.38,5462.3 410.74,5499.71
  other v5: 736.84,1368.2 1600.99,1368.2
GPIO0: J8/J6.78 U1.E7 | length 2887.7
  Top Signal w5: U1.E7@1186.14,3856.88 v2(1204.24,3856.88) ; v1(1889.28,4164.98) 1885.67,4164.98 1851.58,4130.89 1851.58,4030.56 1892.17,3989.97 1892.17,3608.97 1857.8,3574.6 1857.8,2952.11 1910.17,2899.73 1926.33,2883.57 2058.53,2883.57 2133.71,2808.4 2133.71,2666.75 2089.44,2622.48 2002.79,2622.48 1954.95,2574.64 J8/J6.78@1949.99,2574.64
  Middle Signal w4: v2(1204.24,3856.88) 1222.33,3856.88 1411.5,4046.05 1411.5,4122.49 v1(1462.54,4173.53)
  Bottom Signal w5: v1(1462.54,4173.53) 1674.92,4173.53 1707.73,4206.33 1877.41,4206.33 1889.28,4194.46 v1(1889.28,4164.98)
GPIO1: J8/J6.77 U1.A6 | length 2777.3
  Top Signal w4: U1.A6@1240.43,3947.36 1295.98,4002.91 1295.98,4085.5 v1(1318.87,4108.39) ; v1@1320.1,4107.17 v1@1321.85,4108.92
  Top Signal w5: v1(1875.13,4127.2) 1901.17,4101.16 1901.17,3605.25 1866.8,3570.87 1866.8,2955.83 1930.06,2892.57 2062.26,2892.57 2142.71,2812.12 2142.71,2586.85 2080.78,2524.92 2000.27,2524.92 J8/J6.77@1949.99,2474.64 J8/J6.77@1943.57,2474.64
  Bottom Signal w5: v1(1318.87,4108.39) 1327.55,4099.72 1375.92,4099.72 1396.25,4120.05 1686.14,4120.05 1702.09,4136.01 1866.33,4136.01 v1(1875.13,4127.2)
GPIO2: R3.2 U1.B6 | length 2206.6
  Top Signal w4: U1.B6@1222.33,3929.26 1239.88,3929.26 1338.55,4027.94 1338.55,4105.98 1351.41,4118.84 v1(1353.27,4118.84)
  Top Signal w5: R3.2@1795,2767.89 1768.82,2794.08 1768.82,2863.14 1839.8,2934.12 1839.8,3582.06 1874.17,3616.43 1874.17,3982.52 1833.58,4023.11 1833.58,4121.5 1826.68,4128.41 v1(1826.68,4156.26)
  Bottom Signal w5: v1(1353.27,4118.84) 1382.31,4118.84 1392.52,4129.05 1682.41,4129.05 1698.37,4145.01 1778.62,4145.01 1789.88,4156.26 v1(1826.68,4156.26)
GPIO3: R4.2 U1.C6 | length 2077.7
  Top Signal w5: v2@1203.03,3929.26 v2@1203.63,3928.66 ; U1.C6@1203.63,3911.77 U1.C6@1204.24,3911.17 v2(1204.24,3929.26) ; R4.2@1796.02,2655 1759.82,2691.2 1759.82,2866.86 1830.8,2937.85 1830.8,3585.79 1865.17,3620.16 1865.17,3944.82 1850.08,3959.91 v1(1848.77,3959.91)
  Bottom Signal w4: v2(1204.24,3929.26) 1270.59,3995.61 1341.42,3995.61 1341.92,3995.11
  Bottom Signal w5: 1341.92,3995.11 1726.55,3995.11 1761.75,3959.91 v1(1848.77,3959.91)
GPIO4: S4.2 U1.D6 | length 2782.6
  Top Signal w5: U1.D6@1186.14,3893.07 v2(1186.14,3911.17) ; S4.2@1659.46,1983.19 1648.9,1983.19 1599.95,2032.14 1599.95,2072.76 1677.48,2150.29 1677.48,3500.48 1794.1,3617.1 1794.1,3961.94 v1(1775,3981.04)
  Bottom Signal w4: v2(1186.14,3911.17) 1186.14,3929.26 1260.99,4004.11
  Bottom Signal w5: 1260.99,4004.11 1730.28,4004.11 1753.35,3981.04 v1(1775,3981.04)
GPIO4_BP: J4/J2.32 S4.3 | length 2555.4
  Top Signal w5: S4.3@1659.46,2052.09 1659.46,2117.38 1686.48,2144.4 1686.48,3496.75 1803.1,3613.37 1803.1,4113.81 1787.97,4128.94 1787.97,4312.62 J4/J2.32@1949.99,4474.64
GPIO4_CANTX: S4.1 TP7.1 U15.1 | length 1005.8
  Top Signal w5: S4.1@1659.46,1914.29 1719.71,1914.29 1903.74,1730.26 1972,1662 1972,1386 2073.87,1284.13 2190.05,1284.13 2204.39,1269.79 2204.39,1237.69 U15.1@2204.49,1237.59
GPIO5: S4.5 U1.E6 | length 2840.6
  Top Signal w5: U1.E6@1168.05,3874.98 v2(1168.05,3893.07) ; S4.5@1513.79,1983.19 1530.97,2000.37 1547.77,2000.37 1574.99,2027.6 1574.99,2060.53 1668.48,2154.01 1668.48,3504.21 1785.1,3620.83 1785.1,3937.15 1757.17,3965.08 1757.17,4006.96 v1(1757.64,4007.43)
  Middle Signal w4: v2(1168.05,3893.07) 1194.91,3893.07 1313.43,4011.59 v1(1313.43,4028.47)
  Bottom Signal w5: v1(1313.43,4028.47) 1328.79,4013.11 1751.95,4013.11 v1(1757.64,4007.43)
GPIO5_BP: J4/J2.31 S4.6 | length 2598.1
  Top Signal w5: S4.6@1513.79,2052.09 1517.42,2055.72 1517.42,2086.9 v1(1533.26,2102.74) ; v1(1677.48,2106.47) 1695.48,2124.47 1695.48,3493.03 1812.1,3609.64 1812.1,4117.53 1796.97,4132.67 1796.97,4221.62 1822,4246.65 J4/J2.31@1949.99,4374.64
  Bottom Signal w5: v1(1533.26,2102.74) 1535.12,2104.6 1675.62,2104.6 v1(1677.48,2106.47)
GPIO5_CANRX: S4.4 TP8.1 U15.4 | length 976.2
  Top Signal w5: S4.4@1513.79,1914.29 1599.08,1914.29 1855.12,1658.25 1898.75,1658.25 1963,1594 1963,1382.27 1972,1373.27 1972,1371.59 2054.49,1289.09 U15.4@2054.49,1237.59
GPIO6: J4/J2.38 U1.A5 | length 1741.4
  Top Signal w4: U1.A5@1222.33,3965.45 1279.98,4023.1 1279.98,4107.1 1338.59,4165.71
  Top Signal w5: 1338.23,4166.06 1338.23,5021.5 1395.99,5079.26 1945.38,5079.26 J4/J2.38@1949.99,5074.64
GPIO7: J4/J2.37 U1.B5 | length 1597.4
  Top Signal w4: U1.B5@1204.24,3947.36 1221.78,3947.36 1287.98,4013.56 1287.98,4103.79 1347.23,4163.04
  Top Signal w5: 1347.23,4163.04 1347.23,4800.23 v1(1387,4840)
  Bottom Signal w5: v1(1387,4840) 1815.35,4840 J4/J2.37@1949.99,4974.64
GPIO8: R1.2 U1.E3 | length 1903
  Top Signal w5: U1.E3@1113.76,3929.26 v2(1113.76,3947.36)
  Top Signal w6: v1(1755.31,5241.35) 1755.46,5241.35 1786,5271.89 R1.2@1793.61,5271.89 R1.2@1803.8,5282.08
  Middle Signal w5: v2(1113.76,3947.36) 948.15,4112.96 948.15,4193.66 1333.8,4579.31 1333.8,5029.13 1469.7,5165.03 1678.99,5165.03 v1(1755.31,5241.35)
GPIO9: R2.2 U1.F3 | length 1920
  Top Signal w5: U1.F3@1095.67,3911.17 v2(1095.67,3929.26) ; v1(1645.07,5188) 1674.09,5158.98 R2.2@1789.09,5158.98 ; R2.2@1791.51,5156.03 1791.51,5156.57 R2.2@1789.09,5158.98 ; R2.2@1794.46,5150.49 R2.2@1811.33,5167.36 ; R2.2@1794.46,5158.98 R2.2@1789.09,5158.98
  Middle Signal w5: v2(1095.67,3929.26) 939.15,4085.77 939.15,4197.39 1324.8,4583.03 1324.8,5032.86 1479.94,5188 v1(1645.07,5188)
GPIO10: J4/J2.36 U1.B3 | length 1590.5
  Top Signal w4: U1.B3@1168.05,3983.55 1185.59,3983.55 1225.22,4023.18 1225.22,4089.98 1239.53,4104.29 1239.53,4185.95
  Top Signal w5: 1239.53,4185.95 1239.53,4787.71 v1(1262.98,4811.16)
  Bottom Signal w5: v1(1262.98,4811.16) 1264.22,4812.39 1887.74,4812.39 J4/J2.36@1949.99,4874.64
GPIO11: J4/J2.35 U1.B2 | length 1540.7
  Top Signal w4: U1.B2@1149.95,4001.64 1167.5,4001.64 1195,4029.14 1195,4199.73
  Top Signal w5: 1195,4199.73 1195,4628.06 1222.33,4655.4 v1(1222.33,4774.22)
  Bottom Signal w5: v1(1222.33,4774.22) 1949.57,4774.22 J4/J2.35@1949.99,4774.64
GPIO12: J4/J2.13 R17.1 U1.B1 | length 1372.2
  Top Signal w4: U1.B1@1131.86,4019.74 1127.4,4024.2 1127.4,4213.29 v1(1142.09,4227.98)
  Top Signal w5: R17.1@1495.63,4225.62 1488.67,4232.58 v1(1441,4232.58) 1465.53,4257.11 1580.87,4257.11 1609.8,4286.04 1609.8,4301.18 1673.18,4364.56 1739.06,4364.56 1903.15,4528.65 2004,4528.65 J4/J2.13@2049.99,4574.64
  Middle Signal w5: v1(1142.09,4227.98) 1192.75,4278.65 1394.93,4278.65 v1(1441,4232.58)
GPIO13: J8/J6.53 R19.1 U1.C1 | length 3359.6
  Top Signal w4: v1(1093.86,4231.07) 1084.22,4221.44 1084.22,4031.18 U1.C1@1113.76,4001.64
  Top Signal w5: R19.1@1560.53,4225.62 1566.3,4231.39 1585.86,4231.39 v1(1598.94,4244.47)
  Middle Signal w5: v1(1598.94,4244.47) 1598.94,4252.25 1625.36,4278.67 1681.26,4278.67 1735.08,4224.84 1860.55,4224.84 2006.4,4078.99 2006.4,3698.94 1997.66,3690.19 1997.66,2126.97 J8/J6.53@2049.99,2074.64
  Bottom Signal w5: v1(1093.86,4231.07) 1113.29,4231.07 1135.63,4208.73 1563.2,4208.73 v1(1598.94,4244.47)
GPIO14: J4/J2.34 U1.C2 | length 1640.2
  Top Signal w4: 1032.92,4363.75 1032.92,4319.21 1119.16,4232.97 1119.16,4013.79 1131.86,4001.09 U1.C2@1131.86,3983.55
  Top Signal w5: 1032.92,4363.75 1032.92,4633.95 1032.92,4659.3 v1(1048.26,4674.64)
  Bottom Signal w5: v1(1048.26,4674.64) J4/J2.34@1949.99,4674.64
GPIO15: J4/J2.33 U1.C3 | length 1375.2
  Top Signal w5: U1.C3@1149.95,3965.45 v2(1149.95,3983.55) ; v1(1213.79,4127.53) 1204.58,4136.74 1204.58,4558.1 1221.13,4574.64 v1(1222.33,4574.64)
  Bottom Signal w4: v2(1149.95,3983.55) 1213.83,4047.43 1213.83,4082.16 1213.79,4082.2 v1(1213.79,4127.53)
  Bottom Signal w5: v1(1222.33,4574.64) J4/J2.33@1949.99,4574.64
GPIO16: J4/J2.15 U1.C4 | length 1618.9
  Top Signal w5: U1.C4@1168.05,3947.36 v2(1168.05,3965.45) ; v1(1247.08,4081.08) 1248.53,4082.53 1248.53,4700.92 v1(1280.25,4732.64)
  Bottom Signal w4: v2(1168.05,3965.45) 1247.08,4044.49 v1(1247.08,4081.08)
  Bottom Signal w5: v1(1280.25,4732.64) 2007.99,4732.64 J4/J2.15@2049.99,4774.64
GPIO17: J4/J2.14 U1.D4 | length 1683.5
  Top Signal w5: U1.D4@1149.95,3929.26 v2(1149.95,3947.36) ; v1(1176.12,4173.53) 1176.12,4177.26 1183.83,4184.96 1183.83,4686.87 v1(1204.58,4707.62)
  Middle Signal w4: v2(1149.95,3947.36) 1149.95,3965.59 1131.86,3983.68 1131.86,4132.3 1173.08,4173.53 v1(1176.12,4173.53)
  Bottom Signal w5: v1(1204.58,4707.62) 1208.07,4707.62 1216.01,4715.56 1273.01,4715.56 1273.13,4715.44 1287.38,4715.44 1287.5,4715.56 2009.07,4715.56 J4/J2.14@2049.99,4674.64
GPIO18: J1/J3.7 U1.D3 | length 1243.3
  Top Signal w5: J1/J3.7@249.99,4674.64 294.99,4629.64 395.38,4629.64 466.02,4559 v1(536,4559) ; U1.D3@1131.86,3947.36 v2(1131.86,3965.45)
  Middle Signal w5: v1(536,4559) 536,4474.42 875.82,4134.6 v1(876.62,4134.6)
  Bottom Signal w4: v1(876.62,4134.6) 877.34,4133.89 914.01,4133.89 1082.45,3965.45 v2(1131.86,3965.45)
GPIO19: R92.2 U1.D1 | length 4766.5
  Top Signal w4: v1(1048.26,4210.7) 1044.82,4207.26 1044.82,4033.63 1094.91,3983.55 U1.D1@1095.67,3983.55
  Middle Signal w5: v1(451.51,1445.51) 426.53,1470.49 426.53,1605.79 617.39,1796.65 874.64,1796.65 991.85,1913.85 991.85,3306.68 1005.19,3320.01 v1(1005.19,3321.46) ; v1(1048.26,4210.7) 1050.23,4208.73 1477.12,4208.73 1516.47,4169.38 1619.57,4169.38 1708.06,4080.89 1708.06,3651.52 1717.06,3642.52 1717.06,3454.9 v1(1560.78,3298.62)
  Bottom Signal w4: v1(451.51,1445.51) R92.2@492.12,1445.51
  Bottom Signal w5: v1(1005.19,3321.46) 1082.6,3398.88 1195.51,3398.88 1268.86,3325.53 1533.88,3325.53 v1(1560.78,3298.62) v1@1564.75,3294.65
GPIO20: U1.E1 U14.14 | length 3858.8
  Top Signal w4: v1(890.22,4327.06) 884.25,4321.09 884.25,4166.35 U1.E1@1077.57,3965.45 ; v1(1269,2280.75) 1273.87,2280.75 1281.22,2288.1 U14.14@1324.16,2288.1
  Top Signal w5: v1(1642,2327.66) 1659.46,2345.12 1659.46,2469 1632.58,2495.88 1632.58,2524.32 1650.48,2542.22 1650.48,3511.67 1767.1,3628.28 1767.1,3878.05 1713,3932.15 1713,4176.22 1764.29,4227.51 v1(1764.29,4284.38)
  Bottom Signal w5: v1(890.22,4327.06) 914.83,4327.06 939.24,4302.64 1746.03,4302.64 v1(1764.29,4284.38) ; v1(1269,2280.75) 1344.02,2280.75 1350.27,2287 1523,2287 1563.66,2327.66 v1(1642,2327.66)
GPIO20_Q1A: U13.3 U14.12 | length 395.5
  Top Signal w5: U13.3@1136.85,2063.9 1136.85,2102.99 v1@1190.15,2156.28 ; v1(1269,2346.53) 1273.6,2346.53 1280.85,2339.28 U14.12@1324.16,2339.28
  Bottom Signal w5: v1@1190.15,2156.28 1190.15,2267.68 v1(1269,2346.53)
  other v1: 1188.99,2156.28
GPIO21: U1.E2 U14.15 | length 3733.3
  Top Signal w4: v1(907.56,4306.08) 907.56,4160.77 907.56,4159.16 908.68,4158 1082.5,3977.36 ; 1082.53,3977.33 1095.67,3964.19 U1.E2@1095.67,3947.36
  Top Signal w5: v1(1269.66,2250.31) 1271.34,2250.31 1283.58,2262.55 1324.11,2262.55 U14.15@1324.16,2262.51 ; v1(1613.04,2306.75) 1614.58,2308.29 1614.58,2531.77 1632.48,2549.67 1632.48,3519.12 1668.48,3555.12 1704,3590.64 1704,4181.52 1741.72,4219.24 v1(1741.72,4256.72)
  Bottom Signal w5: v1(907.56,4306.08) 908.8,4306.08 921.5,4293.38 1729.65,4293.38 1741.72,4281.31 v1(1741.72,4256.72) ; v1(1269.66,2250.31) 1271.79,2250.31 1285.58,2264.1 1533.26,2264.1 1575.91,2306.75 v1(1613.04,2306.75)
GPIO21_BP: J4/J2.17 U14.1 | length 3437.3
  Top Signal w5: U14.1@1552.5,2236.92 1555.57,2233.85 1604.46,2233.85 v1(1607.52,2230.78) ; J4/J2.17@2049.99,4974.64 2004,4928.65 2004,4840 2018.54,4825.46 2075.28,4825.46 2178.71,4722.03 2178.71,2337.79 2173.18,2332.26 v1(2173.18,2327.66)
  Bottom Signal w5: v1(1607.52,2230.78) 1630.78,2230.78 1716.62,2316.62 2158.06,2316.62 2169.1,2327.66 v1(2173.18,2327.66)
GPIO21_Q1B: U13.4 U14.2 | length 559.2
  Top Signal w5: U13.4@1111.26,2063.9 1111.26,2124.87 1163.43,2177.04 1337.03,2177.04 1417.58,2257.6 1547.6,2257.6 U14.2@1552.5,2262.51
GPIO22: R203.2 U1.D2 | length 4234.8
  Top Signal w4: v1(1061.52,4184.96) 1061.52,4035.23 1113.76,3983 U1.D2@1113.76,3965.45
  Middle Signal w5: v1(568.95,1688.02) 650.57,1769.65 885.83,1769.65 1018.85,1902.67 1018.85,3188.49 1096.5,3266.14 v1(1096.5,3266.51) ; v1(1061.52,4184.96) 1076.3,4199.73 1473.4,4199.73 1512.74,4160.38 1615.84,4160.38 1699.06,4077.17 1699.06,3646.05 1708.06,3637.05 1708.06,3472.15 1534.53,3298.62 v1(1532.25,3298.62)
  Bottom Signal w5: R203.2@568.95,1643.85 v1(568.95,1688.02) ; v1(1096.5,3266.51) 1235.9,3266.51 1285.92,3316.53 1514.35,3316.53 v1(1532.25,3298.62)
GPIO23: U1.F2 U14.4 | length 3348.2
  Top Signal w4: v1(867.55,4297.21) 867.55,4171.73 876.25,4163.03 878.54,4160.75 1054.16,3978.24 1054.16,3970.76 1077.57,3947.36 U1.F2@1077.57,3929.26
  Top Signal w5: U14.4@1552.5,2313.69 1574.77,2313.69 1605.58,2344.51 1605.58,2535.5 1623.48,2553.4 1623.48,3522.85 1695,3594.37 1695,4193.61 1714.82,4213.42 v1(1714.82,4270.26)
  Bottom Signal w5: v1(867.55,4297.21) 892.1,4297.21 904.94,4284.38 1639.91,4284.38 1654.03,4270.26 v1(1714.82,4270.26)
GPIO23_BP: J4/J2.12 U14.3 | length 2916.5
  Top Signal w5: U14.3@1552.5,2288.1 1592.91,2288.1 1603.39,2277.61 1603.39,2263.57 v1(1604.46,2262.51)
  Middle Signal w5: J4/J2.12@2049.99,4474.64 2050.28,4474.36 2167.19,4474.36 v1(2196.54,4445)
  Bottom Signal w5: v1(1604.46,2262.51) 1649.78,2262.51 1712.89,2325.62 2109.62,2325.62 2196.54,2412.54 2196.54,3733.77 2196.8,3734.03 2196.8,4444.74 v1(2196.54,4445)
GPIO23_Q1I: U13.5 U14.5 | length 612
  Top Signal w5: U13.5@1085.67,2063.9 1085.67,2116.97 1154.74,2186.04 1333.3,2186.04 1486.54,2339.28 U14.5@1552.5,2339.28
GPIO24: U1.D7 U11.14 | length 3026.5
  Top Signal w5: v1@878.99,2280.75 883.59,2280.75 891.7,2288.87 948.34,2288.87 U11.14@949.11,2288.1 ; U1.D7@1204.24,3874.98 v2(1222.33,3874.98) ; v1(1649.78,2503) 1649.78,2526.93 1659.48,2536.63 1659.48,3507.94 1776.1,3624.56 1776.1,3893.77 v1(1758.1,3911.77)
  Bottom Signal w4: v2(1222.33,3874.98) 1240.43,3874.98 1322.89,3957.44
  Bottom Signal w5: v1(879.58,2280.75) 881.08,2282.25 894.25,2282.25 1058,2446 1592.78,2446 v1(1649.78,2503) ; 1322.89,3957.44 1738.01,3957.44 1758.1,3937.35 v1(1758.1,3911.77)
GPIO24_BP: J8/J6.58 U11.13 | length 1360
  Top Signal w5: v1@878.55,2314.19 948.61,2314.19 U11.13@949.11,2313.69
  Bottom Signal w5: v1(879.58,2310.02) 1024.56,2455 1576.18,2455 1657.82,2536.63 2027.63,2536.63 2035.94,2544.94 2035.94,2545.43 2049.99,2559.48 J8/J6.58@2049.99,2574.64
GPIO24_Q2A: U11.12 U13.6 | length 585.2
  Top Signal w5: v1@878.99,2339.28 U11.12@949.11,2339.28 ; U13.6@1060.08,2063.9 1060.08,2177.04 v1(1085.67,2202.63)
  Bottom Signal w5: v1(879.58,2339.28) 854.87,2314.57 854.87,2223.05 875.29,2202.63 v1(1085.67,2202.63)
GPIO25: J8/J6.51 U1.B8 | length 3198.7
  Top Signal w4: U1.B8@1258.52,3893.07 1277.88,3893.07 1625.83,4241.02 1625.83,4253.27 v1(1629.27,4256.72)
  Middle Signal w5: v1(1629.27,4256.72) 1689.18,4256.72 1712.97,4232.92 1712.97,4165.08 1741.15,4136.89 1792.74,4136.89 1830.1,4099.53 1830.1,2011.66 1920.76,1921 2003.63,1921 J8/J6.51@2049.99,1874.64
GPIO26: R88.1 R119.1 U1.L10 | length 2901.4
  Top Signal w5: v2(1131.86,3675.93) U1.L10@1131.86,3694.02 ; v1(1531.6,1720.34) 1573.17,1678.77 R88.1@1573.17,1621.08
  Middle Signal w4: v2(1131.86,3675.93) 1131.86,3657.83 1266.42,3523.26 v1@1284.71,3523.26
  Middle Signal w5: v1(1531.6,1720.34) 1521.03,1720.34 1482.34,1759.03 1269.66,1971.71 1269.66,2211.95 1307,2249.29 1307,2528.21 1260.19,2575.01 1260.19,3070.46 1339.89,3150.16 1339.89,3263.54 1564.41,3488.07 1564.41,3501.5 1573.44,3510.53 v1(1573.52,3510.53)
  Bottom Signal w4: v1(1531.6,1720.34) 1589.58,1720.34 1629.28,1680.64 R119.1@1629.28,1653 ; R119.1@1619.47,1662.81 R119.1@1629.28,1653 ; R119.1@1629.28,1649.06 R119.1@1629.28,1653
  Bottom Signal w5: v1@1284.71,3523.26 1313.78,3494.19 1507.07,3494.19 1527.51,3514.63 1569.41,3514.63 v1(1573.52,3510.53)
  other v1: 1289.61,3527.25
GPIO27: R107.1 U1.D11 U17.11 U20.11 | length 4079.6
  Top Signal w5: U20.11@831.33,1338.67 v1@865.04,1338.67 ; U1.D11@1276.62,3802.59 v2(1294.71,3802.59) ; U17.11@1695.48,1338.67 1711.71,1338.67 v1(1724.25,1326.13)
  Middle Signal w4: v2(1294.71,3802.59) 1368.48,3728.83 1404.4,3728.83 1423.07,3710.16 1423.07,3700.25 v1(1426.13,3697.18)
  Middle Signal w5: v1(865.45,1340.94) 894.74,1311.66 1709.78,1311.66 v1(1724.25,1326.13) 1731.94,1326.13 1829.37,1423.56 1829.37,1661.96 1458.31,2033.02 1458.31,3318.33 1672.03,3532.05 1672.03,3622.16 1663.06,3631.13 1663.06,3671.77 v1(1647.35,3687.48)
  Bottom Signal w5: v1(1426.13,3697.18) 1427.86,3697.18 1438.3,3686.74 1646.61,3686.74 v1(1647.35,3687.48) ; v1(1724.25,1326.13) 1765.1,1326.13 R107.1@1770.38,1331.41
GPIO28: R113.2 R116.1 U1.K8 | length 3126.7
  Top Signal w4: v2(1113.76,3730.21) U1.K8@1113.76,3748.31
  Top Signal w5: R113.2@1852.38,1502 v1(1885.4,1502)
  Middle Signal w4: 1101.06,3669.98 1101.06,3699.28 1113.76,3711.98 v2(1113.76,3730.21)
  Middle Signal w5: v1(965.04,1947.65) 965.04,3423.78 1101.06,3559.8 1101.06,3669.98
  Bottom Signal w5: v1(965.04,1947.65) 1054.69,1858 1629,1858 1885.4,1601.6 v1(1885.4,1502) 1884.71,1502.69 R116.1@1817.62,1502.69
GPIO29: R111.1 R117.1 U1.L8 | length 2845.1
  Top Signal w5: v2(1095.67,3712.12) U1.L8@1095.67,3730.21 ; v1(1777.17,1473.7) 1778.24,1472.63 1792.26,1472.63 1802.51,1462.38 1802.51,1448.63 R111.1@1805.13,1446
  Middle Signal w5: v1(1387.63,2642) 1387.63,2604.66 1369.87,2586.9 1369.87,2083.28 1755,1698.15 1755,1495.87 v1(1777.17,1473.7)
  Bottom Signal w5: v2(1095.67,3712.12) 1071.57,3712.12 1062.01,3702.56 1061.93,3702.56 889.86,3530.48 889.86,3413.27 889.86,3411.2 1387.63,2913.43 v1(1387.63,2642) ; v1(1777.17,1473.7) 1801.43,1473.7 1813.15,1461.98 1813.15,1449.73 R117.1@1817.62,1445.25
GPIO30: R106.1 U1.L9 U12.6 | length 724.8
  Top Signal w5: v1(1094.91,3460.43) 1075.23,3440.75 1075.23,3254.61 1092.34,3237.5 R106.1@1213.79,3237.5 ; v2(1113.76,3694.02) U1.L9@1113.76,3712.12 ; U12.6@1149.46,3238.18 R106.1@1213.79,3238.18
  Bottom Signal w4: v1(1094.91,3460.43) 1094.91,3542.75 1045.01,3592.65 1045.01,3625.27 v2(1113.76,3694.02)
GPIO32: J8/J6.74 U1.F12 | length 2122.8
  Top Signal w4: U1.F12@1258.52,3748.31 1275.7,3748.31 1360.87,3663.14 1417.47,3663.14 1437.28,3643.33 1478.02,3643.33 1478.09,3643.26 1481.82,3643.26 1490.95,3634.12 v1(1495.82,3634.12)
  Top Signal w5: v1(1803.68,3564.15) 1803.68,2936.18 1741.82,2874.32 1741.82,2382.82 J8/J6.74@1949.99,2174.64
  Bottom Signal w5: v1(1495.82,3634.12) 1539.65,3634.12 1567.39,3606.38 1761.45,3606.38 v1(1803.68,3564.15)
GPIO33: R139.1 U1.L7 U18.1 | length 3557.9
  Top Signal w5: v2(1077.57,3730.21) U1.L7@1077.57,3748.31 ; R139.1@1114.84,438.62 1112.82,440.65 U18.1@1112.82,533.72 1106.14,540.4 1106.14,557.97 1070.02,594.09 1070.02,1323.81 v1(1127.02,1380.8)
  Middle Signal w5: v1(1127.02,1380.8) 1153.79,1407.58 1153.79,3101.19 v1(1130.2,3124.77)
  Bottom Signal w5: 1060.39,3713.74 880.86,3534.21 880.86,3374.12 v1(1130.2,3124.77) ; 1060.43,3713.7 1076.94,3730.21 v2(1077.57,3730.21)
GPIO34: J5/J7.50 U1.K7 | length 2427.6
  Top Signal w5: v2(1095.67,3748.31) U1.K7@1095.67,3766.4
  Middle Signal w4: 1076.11,3710.79 1095.67,3730.35 v2(1095.67,3748.31)
  Middle Signal w5: J5/J7.50@249.99,1874.64 297.35,1922 363,1922 515.64,2074.64 714.68,2074.64 831.49,2191.45 831.49,2344.04 869.42,2381.97 869.42,3455.78 844.45,3480.75 844.45,3495.84 1059.41,3710.79 1076.11,3710.79
GPIO35: J5/J7.49 U1.N8 | length 2556.3
  Top Signal w4: v1(861.65,3488.71) 1058.8,3685.86 1058.8,3693.35 U1.N8@1059.47,3694.02
  Middle Signal w5: J5/J7.49@249.99,1974.64 198,1922.65 198,1858 232,1824 390.08,1824 631.72,2065.64 710.95,2065.64 718.41,2065.64 840.49,2187.73 840.49,2340.31 878.42,2378.24 878.42,3471.94 v1(861.65,3488.71)
GPIO36: J8/J6.71 U1.N11 | length 2823.6
  Top Signal w4: 1035.34,3561.31 U1.N11@1113.76,3639.74
  Top Signal w5: v1(851.78,2142.8) 851.78,2146.38 842.45,2155.71 842.45,2410.56 1035.34,2603.44 1035.34,3561.31
  Bottom Signal w5: v1(851.78,2142.8) 851.78,2140.91 1118.06,1874.64 J8/J6.71@1949.99,1874.64
GPIO37: J8/J6.72 U1.M11 | length 2781.1
  Top Signal w4: 1045.01,3553.64 1118.7,3627.33 1118.9,3627.33 1131.86,3640.29 U1.M11@1131.86,3657.83
  Top Signal w5: v1(861.79,2177.04) 861.79,2179.79 853.11,2188.47 853.11,2408.49 1045.01,2600.38 1045.01,3553.64
  Bottom Signal w5: v1(861.79,2177.04) 861.79,2174.41 1070.69,1965.51 1940.86,1965.51 J8/J6.72@1949.99,1974.64
GPIO38: U1.L11 U8.10 | length 2871.8
  Top Signal w5: v2(1149.95,3657.83) U1.L11@1149.95,3675.93 ; U8.10@1474.6,5261.03 1520.45,5261.03 1581.6,5199.88 v1(1581.6,5131)
  Middle Signal w5: v1(1581.6,5131) 1581.6,4227.98 1595.2,4214.38 1638.21,4214.38 1733.7,4118.89 1785.28,4118.89 1812.1,4092.08 1812.1,3805.8 1730.52,3724.23 1730.52,3447.7 1719.68,3436.86 1719.68,3418.36 v1(1722.19,3415.86)
  Bottom Signal w4: v2(1149.95,3657.83) 1188.99,3618.79
  Bottom Signal w5: 1188.99,3618.79 1188.99,3491.37 1264.5,3415.86 v1(1722.19,3415.86)
GPIO38_BP: J5/J7.44 J5/J7.45 U8.9 | length 3851.2
  Top Signal w5: J5/J7.45@249.99,2374.64 J5/J7.44@249.99,2474.64 ; v1(1429.06,5241.35) U8.9@1474.6,5241.35
  Bottom Signal w5: J5/J7.44@249.99,2474.64 128,2596.63 128,4537 221.26,4630.26 665.36,4630.26 759.67,4724.56 912.27,4724.56 v1(1429.06,5241.35)
GPIO38_SCITX: U8.2 U9.2 | length 231.4
  Top Signal w5: U9.2@1118.5,5223.29 1118.5,5256.13 1132.4,5270.03 1234.3,5270.03 1262.98,5241.35 U8.2@1299.4,5241.35
GPIO40: R105.1 U1.N12 U12.5 | length 577.7
  Top Signal w4: 1055.19,3544.98 U1.N12@1131.86,3621.64
  Top Signal w5: 1055.19,3544.98 1054.01,3543.79 1054.01,3247.05 1112.87,3188.18 U12.5@1149.46,3188.18 R105.1@1200.44,3188.18
GPIO41: J8/J6.73 U1.M12 | length 2208.2
  Top Signal w4: U1.M12@1149.95,3639.74 1149.95,3621.82 1136.86,3608.73 1136.86,3574.97 v1(1232.23,3479.6)
  Top Signal w5: v1(1764.29,3428.14) 1764.29,2909.52 1732.82,2878.05 1732.82,2291.82 J8/J6.73@1949.99,2074.64
  Bottom Signal w5: v1(1232.23,3479.6) 1249.78,3462.06 1294.95,3442.06 1355.7,3434.37 1758.06,3434.37 v1(1764.29,3428.14)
